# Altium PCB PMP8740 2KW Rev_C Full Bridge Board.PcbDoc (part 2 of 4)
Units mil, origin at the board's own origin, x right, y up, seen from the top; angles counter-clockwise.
Board outline 10366.14 x 5900 mil, 2 copper layers (Top Layer, Bottom Layer), stack 62 mil thick; 355 components, 213 nets, 1059 pads, 574 vias.
Unrouted connection lines stored in the file: 2.
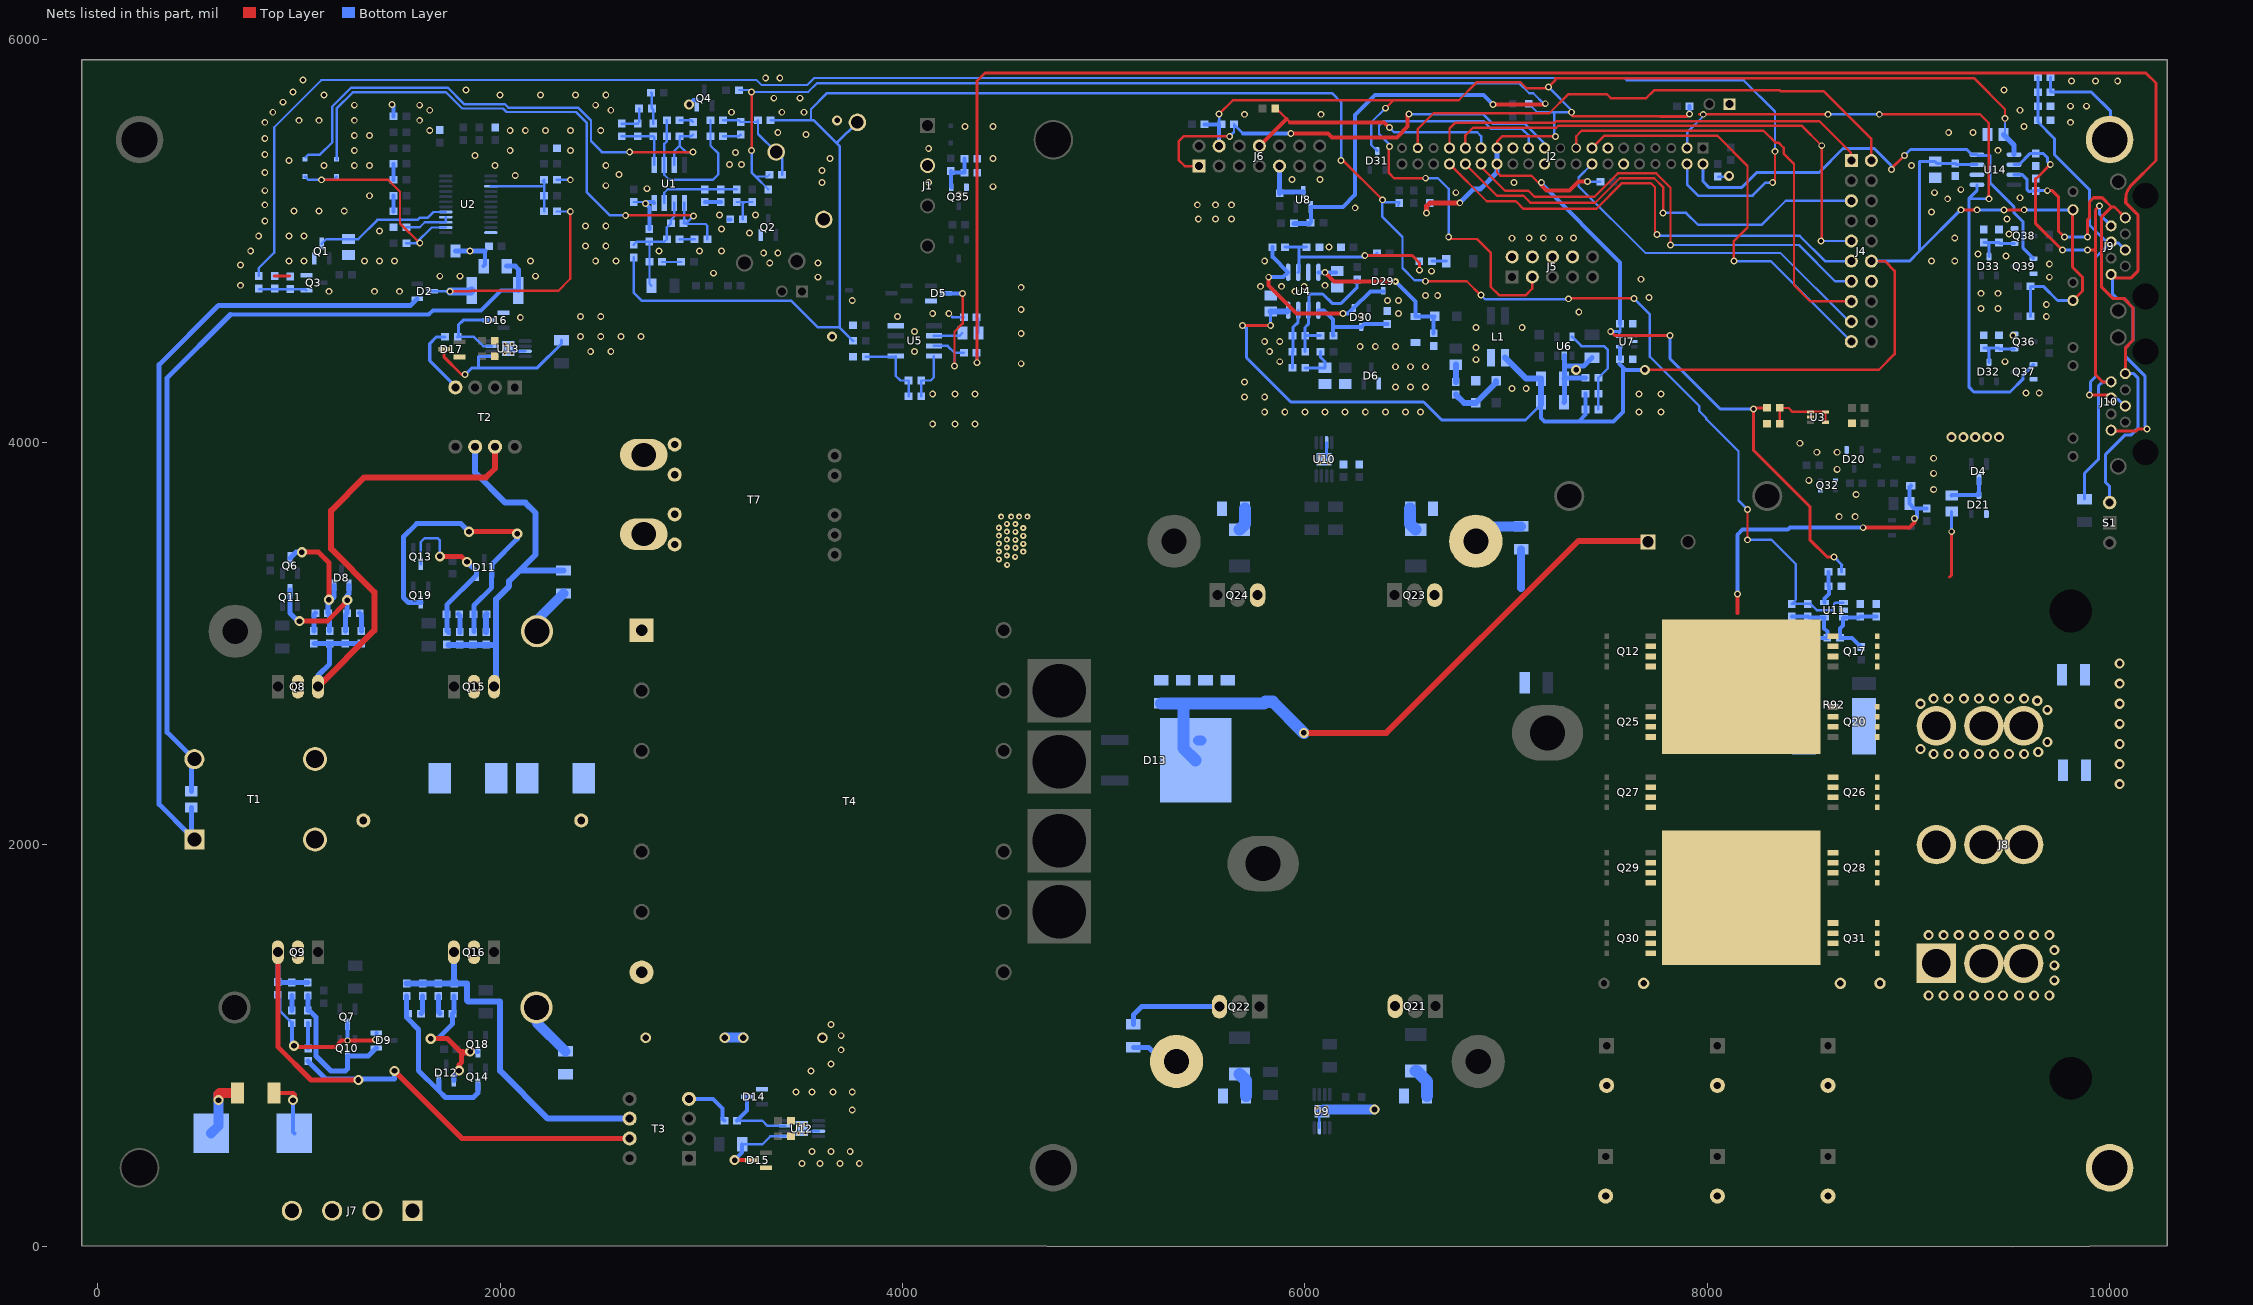
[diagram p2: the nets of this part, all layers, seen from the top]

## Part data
C1: "CAP, CERM, 2200 pF, 50 V, +/- 5%, C0G/NP0, 0603"
C2 C7 C11 C14 C17 C30 C31 C40 C41 C44 C45 C51 C52 C60 C63 C65 C68 C70 C94 C95 C97 C98: "CAP, CERM, 0.1uF, 50V, +/-10%, X7R, 0603"
C3 C10 C22 C23 C24 C42 C43 C61 C62 C69 C71 C73: "CAP, CERM, 1uF, 25V, +/-10%, X7R, 0603"
C4 C88: "CAP, CERM, 2.2uF, 16V, +/-10%, X7R, 0805"
C5 C15 C90 C91 C96: library part C1608X7R2A223K
C6 C16: "CAP, CERM, 0.22uF, 16V, +/-10%, X7R, 0603"
C8: "CAP, CERM, 0.47uF, 16V, +/-10%, X7R, 0805"
C9 C20 C28: "CAP, CERM, 330pF, 50V, +/-5%, C0G/NP0, 0603"
C12: "CAP, CERM, 560pF, 50V, +/-5%, C0G/NP0, 0603"
C13 C36 C37 C38 C39 C46 C47 C49 C50 C66 C67 C72: "CAP, CERM, 0.022uF, 100V, +/-10%, X7R, 0603"
C18: library part CAP_ECQ-E6225KF, "Capacitor, Polyester Film, vvV, ±10%"
C19 C29 C53 C54 C55 C56: library part CAP_ZL_12.5MM_SERIES, "Capacitor, Electrolytic, KZM series, 50V, 105C, 20%"
C21: "CAP, CERM, 22uF, 6.3V, +/-20%, X5R, 0805"
C25: "CAP, CERM, 4.7uF, 25V, +/-10%, X7R, 1206"
C26 C27: "CAP, CERM, 10uF, 10V, +/-20%, X7R, 1206"
C32 C33 C34 C35: "CAP, CERM, 1000pF, 1000V, +/-10%, X7R, 1206"
C48 C58 C59: "CAP, CERM, 10uF, 50V, +/-10%, X7R, 1210"
C57: "CAP, CERM, 0.22 µF, 25 V, +/- 10%, X7R, 0805"
C64 C74 C75 C76: "CAP, CERM, 0.1uF, 250V, +/-10%, X7R, 1206"
C77 C78: "CAP, CERM, 2200pF, 250V, +/-20%, E, Cap, 7x12x9 mm"
C79: "CAP, CERM, 220pF, 50V, +/-5%, C0G/NP0, 0603"
C80: "CAP, CERM, 0.01 µF, 50 V, +/- 10%, X7R, 0603"
C81: "CAP, CERM, 100uF, 10V, +/-20%, X5R, 1206_190"
C82: "CAP, CERM, 1000pF, 50V, +/-10%, X7R, 0603"
C83 C86: "CAP, CERM, 68pF, 50V, +/-5%, C0G/NP0, 0603"
C84 C87 C89 C92 C93: "CAP, CERM, 1uF, 16V, +/-10%, X7R, 0805"
C85: "CAP, CERM, 2700pF, 50V, +/-5%, C0G/NP0, 0603"
C99: "CAP, CERM, 1000 pF, 50 V, +/- 5%, C0G/NP0, 0603"
C100 C101 C102 C103: "CAP, CERM, 470 pF, 500 V, +/- 10%, X7R, 1206"
D1 D3 D28: "Diode, Schottky, 30 V, 0.2 A, SOD-323"
D2 D4 D6 D19 D20 D21 D22 D29 D30 D31 D32 D33: "Diode, Switching, 200V, 0.2A, SOT-23"
D5 D8 D9 D11 D12 D14 D15 D16 D17: "Diode, Schottky, 30V, 0.2A, SOT-23"
D7 D10: "Diode, Ultrafast, 600V, 3A, SMC"
D13: "Diode, Ultrafast, 200V, 8A, DDPAK"
D18: "Diode, Zener, 13 V, 500 mW, SOD-123"
D23 D24 D25 D27: "Diode, Schottky, 60 V, 1 A, SOD-123F"
D26: "Diode, Zener, 5.1 V, 500 mW, SOD-123"
HS1 HS2 HS3 HS4: "Heatsink,  Vertical-mount"
HS5 HS6: "Heatsink, SMT"
J1: "Header (shrouded), 5.08 mm, 4x1, R/A, TH"
J2: "Header, 2mm, 20x2, Gold, TH"
J3 J11: "Header, 100mil, 2x1, Gold, TH"
J4: "Header (shrouded), 100mil, 10x2, Gold plated, TH"
J5: "Header (shrouded), 100mil, 5x2, Gold, TH"
J6: "Header (shrouded), 100 mil, 7x2, Gold plated, TH"
J7: "Header, 4POS, 200mil, Vertical, Tin, TH"
J8: "Header (shrouded), 15 mm, 3x3, R/A, TH"
J9 J10: "RJ-45, Right Angle, Yellow/Green LED, tab up"
J18 J19: "Power Connector, 8AWG, SILVER W/PIN, TH"
L1: library part 744878004, "Coupled inductor, 10 µH, 1 A, 0.14 ohm, +/- 20%, SMD"
L2: "Inductor, Shielded Drum Core, WE-Perm, 2.3uH, 17A, 0.0037 ohm, SMD"
L3: "Inductor, Wirewound, 7.9uH, 60A, SMD"
Q1 Q2 Q3 Q4 Q35 Q36 Q37 Q38 Q39: "MOSFET, N-CH, 50V, 0.22A, SOT-23"
Q5: library part "MMBT2222A, Fairchild Semiconductor", "Transistor, NPN, 40V, 0.15A, SOT-23"
Q6 Q7 Q13 Q14: library part "MMBT3904, Fairchild Semiconductor", "Transistor, NPN, 40V, 0.2A, SOT-23"
Q8 Q9 Q15 Q16: "MOSFET, N-CH, 550V, 17A, TO-220AB"
Q10 Q11 Q18 Q19: library part "MMBT3906, Fairchild Semiconductor", "Transistor, PNP, 40V, 0.2A, SOT-23"
Q12 Q17 Q20 Q25 Q26 Q27 Q28 Q29 Q30 Q31: "MOSFET, N-CH, 60V, 172A, SON 5x6mm"
Q21 Q22 Q23 Q24: library part IPP50R199CP, "MOSFET, N-CH, 150V, 83A, TO-220AB"
Q32: library part "MMDT3904-7-F, Diodes Inc.", "Transistor, Dual NPN, 160 V, 0.2 A, SOT-363"
Q33: library part "MMBT2907A, Fairchild Semiconductor", "Transistor, PNP, 60 V, 0.8 A, SOT-23"
Q34: library part BSS84-7-F, "MOSFET, P-CH, -30 V, -3 A, SOT-23"
R1 R114: "RES, 0 ohm, 1%, 0.1W, 0603"
R2 R31 R33 R51 R55 R56 R57 R63 R66 R80 R111 R115: "RES, 10.0k ohm, 1%, 0.1W, 0603"
R3: "RES, 68.1 k, 1%, 0.1 W, 0603"
R4 R24 R30 R45 R52 R104 R108: "RES, 100k ohm, 1%, 0.1W, 0603"
R5 R6: "RES, 8.25k ohm, 1%, 0.1W, 0603"
R7: "RES, 15.4k ohm, 1%, 0.1W, 0603"
R8: library part CRCW06031R00FKEA
R9 R10 R11: "RES, 49.9k ohm, 1%, 0.1W, 0603"
R12 R39: "RES, 49.9 ohm, 1%, 0.1W, 0603"
R13: "RES, 33.2 k, 1%, 0.25 W, 1206"
R14: "RES, 2.49k ohm, 1%, 0.1W, 0603"
R15 R42: "RES, 60.4k ohm, 1%, 0.1W, 0603"
R16: "RES, 4.64k ohm, 1%, 0.1W, 0603"
R17: "RES, 348 ohm, 1%, 0.1W, 0603"
R18: "RES, 562, 1%, 0.1 W, 0603"
R19: "RES, 2.37k ohm, 1%, 0.1W, 0603"
R20: "RES, 90.9k ohm, 1%, 0.1W, 0603"
R21 R43: library part CRCW060313K0FKEA
R22: "RES, 13.0k ohm, 1%, 0.1W, 0603"
R23 R41 R44 R61: "RES, 47.5 k, 1%, 0.1 W, 0603"
R25 R26 R35 R46 R47 R105 R118 R121: "RES, 4.75k ohm, 1%, 0.1W, 0603"
R27 R28 R49 R58 R59 R60 R83 R84 R93 R94 R123: "RES, 1.00k ohm, 1%, 0.1W, 0603"
R29 R50: "RES, 102 k, 1%, 0.1 W, 0603"
R34: "RES, 16.2, 1%, 1 W, 2512"
R36: library part CRCW12061K00FKEA, "RES, 0 Ohm, 0.25 W, 1206"
R37: "RES, 150 k, 1%, 0.1 W, 0603"
R38 R110: "RES, 33.2 ohm, 1%, 0.1W, 0603"
R40: "RES, 28.0k ohm, 1%, 0.1W, 0603"
R48 R70 R71 R72 R75 R76 R77 R81 R82 R85 R88 R89 R90: "RES, 100 ohm, 1%, 0.1W, 0603"
R53: "RES, 10.0k ohm, 1%, 0.125W, 0805"
R54: "RES, 30.1k ohm, 1%, 0.1W, 0603"
R62: "RES, 105k ohm, 1%, 0.1W, 0603"
R64: "RES, 20.0k ohm, 1%, 0.1W, 0603"
R65 R67 R109 R112 R113: "RES, 22.1k ohm, 1%, 0.1W, 0603"
R68 R125 R126 R127 R128: "RES, 10.0, 1%, 0.75 W, 2010"
R69: "RES, 100k ohm, 5%, 0.125W, 0805"
R73 R74 R86 R87: "RES, 10.0, 1%, 0.25 W, 1206"
R78 R79 R95 R96 R97 R99: "RES, 2.21 ohm, 1%, 0.25W, 1206"
R91: "RES, 47.5 ohm, 1%, 0.125W, 0805"
R92: library part R-WSL3637, "Resistor, precision shunt,  5W, 1%,"
R98: library part RTO020F680R0JTE3, "RES, 1Kohm, 5%, 20W, TH"
R100 R101: "RES, 165k ohm, 1%, 0.1W, 0603"
R102: "RES, 27.4 k, 1%, 0.1 W, 0603"
R103: "RES, 169 k, 1%, 0.1 W, 0603"
R106: "RES, 332 ohm, 1%, 0.1W, 0603"
R107 R119 R122: "RES, 1.00 M, 1%, 0.1 W, 0603"
R116: "RES, 121, 1%, 0.25 W, 1206"
R117 R120: "RES, 100, 1%, 0.1 W, 0603"
R124: library part CRCW06031K00FKEA
RT1 RT2: library part B57153S150M, "Thermistor PTC, 15 ohm, 8.5mm Disc"
S1: "Switch, Slide Flush actuator, SPDT, R/A, TH"
T1: library part CS4200V-01L, "Transformer , Current sense, 1:100, 20 mH, TH"
T2 T3: "Drive Gate Transformer, 900uH"
T4: "Transformer, 3.2mH, TH"
T7: "Transformer, 300uH, TH"
TP1: "Test Point, Compact, Black, TH"
TP2 TP5: "Test Point, Compact, Orange, TH"
TP3 TP6: "Test Point, Compact, Red, TH"
TP4 TP7 TP8 TP13: library part 8600-0-05-80-00-00-03-0, "PCB Pin, solderless Pressfit, Tin over Nickel"
U1: "IC, Precision Dual Operational Amplifiers"
U2: "Green Phase-Shifted Full-Bridge Controller with Synchronous Rectification with Current Control, 97 % Duty Cycle, -40 to +125 degC, 24-pin TSSOP (PW), Green (RoHS & no Sb/Br)"
U3: "Analog Temperature Sensor with Class-AB Output, 5-pin SC-70"
U4: library part TLC2272ACD, "Advanced LinCMOS(TM) Rail-to-Rail Dual Operational Amplifier, 4.4 to 16 V, 0 to 70 degC, 8-pin SOIC (D0008A), Green (RoHS & no Sb/Br)"
U5: library part UCC2900XD, "IC, Advance 8-p Load -Share Controller."
U6: "4.5V to 18V Input, 500mA Synchronous Step Down SWIFT Converter, DBV0005A"
U7: library part TPS71533DCK, "50 mA, 24 V, 3.2-mA Supply Current Low-Dropout Linear Regulator, DCK0005A"
U8: "PRECISION PROGRAMMABLE REFERENCE, DBZ0003A"
U9 U10 U12 U13: "Dual 5-A High-Speed Low-Side Gate Driver, DGN0008D"
U11: library part OPA376AIDBV, "Low-Noise, Low Quiescent Current, Precision Operational Amplifier e-trim Series, DBV0005A"
U14: "CAN Transceiver with Fast Loop Times for Highly Loaded Networks, 85 mA, 5 V, -40 to 125 degC, 8-pin SOIC (D), Green (RoHS & no Sb/Br)"

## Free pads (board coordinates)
  round 196.85 hole 177.17: 0(207.52,393.7) 0(4750,5503.94)
  round 236.22 hole 177.17: 0(207.52,5503.94) 0(4750,393.7)

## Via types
v1: diameter 34, hole 20, Top Layer to Bottom Layer, 367 vias
v2: diameter 50, hole 28, Top Layer to Bottom Layer, 60 vias
v3: diameter 34, hole 20, Top Layer to Bottom Layer, tented both sides, 45 vias
v4: diameter 30, hole 12, Top Layer to Bottom Layer, tented both sides, 34 vias
v5: diameter 50, hole 28, Top Layer to Bottom Layer, tented both sides, 33 vias
v6: diameter 19.68, hole 7.87, Top Layer to Bottom Layer, tented both sides, 20 vias
v7: diameter 34, hole 22, Top Layer to Bottom Layer, 11 vias
v8: diameter 34, hole 15, Top Layer to Bottom Layer, 3 vias
v9: diameter 30, hole 20, Top Layer to Bottom Layer, tented both sides, 1 vias

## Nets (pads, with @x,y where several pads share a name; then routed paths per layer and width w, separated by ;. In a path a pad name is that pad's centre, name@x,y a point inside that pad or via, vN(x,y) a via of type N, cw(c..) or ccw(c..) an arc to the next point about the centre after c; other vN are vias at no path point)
+3V45: C24.1 C92.1 D31.3 J2.27 J2.28 J6.4 R26.2 R31.2 R38.2 R48.2 R51.2 R55.1 R61.1 R115.2 U7.5 U14.5 | length 10673.1
  Top Layer w12: v1(5572.7,5630.63) 5642.07,5700 6440,5700 ; v1(6400,5660) 6440,5700 ; J2.28@6954.76,5383.07 6954.76,5341.73 6971.5,5325 7125,5325 v1@7175,5275 ; J2.27@6954.76,5461.81 6955,5462.05 6955,5495 6980,5520 v1(7245,5520) v1@7250,5520 ; v1(7325,5640) 7325,5625 7330,5620 7765,5620 ; v1@9480,5595 v1(9480,5610) 9480,5655 9325,5810 7245,5810 7245,5800 v1(7210,5765) 7210,5760 7100,5760 7070,5790 6855,5790 6765,5700 6440,5700
  Top Layer w15: v1(7520,4550) 7540,4530 v1(7815,4530) ; 7765,5620 7900,5620 7905,5625 v3(7911.5,5631.5) ; R38.2@8297.28,4170.47 8296.81,4170 8235,4170 v1(8230,4165) 8230,3960 8510,3680 8510,3515 8595,3430 v1(8630,3430)
  Top Layer w20: v1(7175,5290) 7175,5275 7200,5250 7315.51,5250 7360.51,5295 v1(7405,5295)
  Top Layer w25: v1(6605,5140) 6605,5173.5 6621.5,5190 v1(6770,5190)
  Bottom Layer w12: v1(5572.7,5630.63) 5573.66,5629.67 5573.66,5579.92 R61.1@5573.66,5568.9 ; D31.3@6360,5447.24 6330,5477.24 6330,5590 v1(6400,5660) ; R51.2@7112.24,5682.28 7154.53,5640 7239.76,5640 ; v1@7210,5760 v1(7210,5765) 7325,5650 v1(7325,5640) 7239.76,5640 ; v1(7245,5520) 7239.76,5525.24 7239.76,5640 ; v1(7405,5295) R55.1@7468.5,5295 ; U7.5@7562.6,4525.91 7562.6,4545.91 7566.69,4550 C24.1@7566.69,4587.87 ; C92.1@9472.5,5529.38 9480,5536.88 v1(9480,5610)
  Bottom Layer w15: v1(7520,4550) 7566.69,4550 ; v1(7815,4530) 7815,4415 8065,4165 v1(8230,4165) ; v1(8630,3430) 8670,3390 8666.5,3386.5 R48.2@8666.5,3355
  Bottom Layer w20: R26.2@5501.5,5580 5501.57,5579.92 R61.1@5573.66,5579.92 ; J6.4@5573.66,5472.44 R61.1@5573.66,5568.9 ; 6872.09,5259.06 6876.02,5262.99 ; v1(7175,5290) 7180,5290 7180,5280 7566.69,4893.31 C24.1@7566.69,4587.87 ; R115.2@7911.5,5670 v3(7911.5,5631.5) ; v3(7911.5,5631.5) 7905,5625 v3(7911.5,5631.5)
  Bottom Layer w25: v1(6605,5140) 6605,5173.5 R31.2@6620,5188.5 ; v1(6770,5190) 6839.06,5259.06 6872.09,5259.06 ; 6876.02,5262.99 6954.76,5341.73 J2.28@6954.76,5383.07 J2.27@6954.76,5461.81 ; C92.1@9472.5,5529.38 9525.02,5476.86 U14.5@9525.02,5429.38
+5V: C23.1 C26.1 C27.1 C28.1 C84.1 C93.1 C94.1 J4.12 J9.10 J9.12 L1.2 R62.2 R118.1 R121.1 U4.8 U7.4 U14.3 | length 8096.7
  Top Layer w12: v2(7690,4359.45) 8852.4,4359.45 8931.14,4438.19 8931.14,4851.57 8882.72,4900 J4.12@8815.79,4900
  Top Layer w15: v1(5690,4580) 5820,4580 5830,4590 v1(5830,4580) ; v1(9260.32,5155.31) v1(9340,5155.31) ; v1(9475,5155) v1@9575,5155 ; J9.12@9817.72,4704.53 9865,4751.81 9865,4820 9815,4870 9815,5152.6 J9.10@9817.72,5155.31
  Bottom Layer w15: v1(5690,4580) 5700,4570 5710,4570 5710,4420 5930,4200 6590,4200 6680,4110 7096.06,4110 C27.1@7173.27,4187.2 ; v1(5830,4580) C84.1@5830,4650 ; J4.12@8815.79,4900 9005,4900 9055,4950 ; v1(9260.32,5155.31) 9055,4950 ; v1(9340,5155.31) 9340.32,5155 v1(9475,5155) ; U14.3@9339.99,5379.38 9239,5379.38 C94.1@9232.5,5385.88 9141.01,5385.88 C93.1@9132.5,5394.38 9131.89,5395 9055,5395 9055,4950 ; v1@9575,5155 v1(9575.32,5155.31) J9.10@9817.72,5155.31 ; R118.1@9606.5,4625 R121.1@9606.5,4775 9670,4775 9740.47,4704.53 J9.12@9817.72,4704.53
  Bottom Layer w20: C27.1@7173.27,4198.03 7173.27,4121.26 7190.98,4103.54 7361.42,4103.54 ; R62.2@7395.71,4241.34 C28.1@7395.71,4162.6 7395.71,4137.84 7361.42,4103.54 ; 7562.6,4388.11 7580,4370.71 ; U7.4@7562.6,4474.72 7566.69,4470.63 C23.1@7566.69,4412.87 ; v2(7690,4359.45) 7689.45,4360 7590,4360 7590,4360.71 7580,4370.71 ; 7361.42,4103.54 7533.54,4103.54 7580,4150 7580,4370.71
  Bottom Layer w30: C84.1@5830,4650 5911.28,4650 U4.8@5916.79,4655.51 ; L1.2@6995.43,4420.67 7099.96,4316.14 C26.1@7173.27,4316.14 C27.1@7173.27,4198.03 C27.1@7173.27,4187.2
+5VREF: R25.1 R46.1 R60.1 R63.2 R102.2 U8.1 | length 6474.8
  Top Layer w12: v3(3250,5450) 3250,5583.9 3250.04,5583.86 v3(3250.04,5741.34)
  Top Layer w20: v1(6935.08,5678.35) 7190.98,5678.35 v1(7195,5682.36)
  Bottom Layer w10: R46.1@3186.5,5750 3241.38,5750 v3(3250.04,5741.34) 3531.34,5741.34 3575,5785 ; 3269.8,5320 3328.5,5320 R102.2@3338.5,5330
  Bottom Layer w12: v3@3250,5446.1 3250,5339.8 3269.8,5320 R25.1@3332.72,5257.09 ; 3575,5785 7064.65,5785 7115.31,5734.34 7134.99,5734.34 7190.98,5678.35 v1(7195,5682.36)
  Bottom Layer w20: R60.1@6023.66,5087.8 6029.57,5093.7 U8.1@6029.57,5168.5 6188.5,5168.5 6250,5230 6250,5627.13 6347.65,5724.77 6888.65,5724.77 v1(6935.08,5678.35)
  Bottom Layer w25: R63.2@5944.92,5087.8 R60.1@6023.66,5087.8
+390V: J7.1 J7.2 L2.1 R68.1 | length 385.7
  Top Layer w20: R68.1@879.49,765 970,765 980,755 980,735 975,730 v2(970,730)
  Bottom Layer w20: v2(970,730) 975,730 980,735 980,755 970,765 970,571.69 L2.1@976.69,565
-5V: C73.1 C87.1 D24.2 D26.2 U4.4 | length 853.1
  Top Layer w20: v1(6100,4844.49) 6145.47,4799.02 v8(6449.88,4799.02)
  Bottom Layer w20: U4.4@6066.79,4844.49 v1(6100,4844.49) C87.1@6154.49,4844.49 ; v8(6449.88,4799.02) 6550,4698.9 D26.2@6550,4624.47 6550.53,4625 D24.2@6644.88,4625 6640,4620.12 C73.1@6640,4541.5
AVCC: J2.12
"BACKLIGHT P1.0": J2.37 J4.2 | length 2652.3
  Top Layer w12: J2.37@6561.06,5461.81 6561.06,5556.3 6639.8,5635.04 7214.61,5635.04 7309.57,5730 7500,5730 7520,5710 7696.83,5710 7735.67,5748.83 8360.65,5748.83 8364.21,5745.28 8576.81,5745.28 8815.79,5506.3 J4.2@8815.79,5400
CAN_RX: J2.2 Q39.1 U14.4 | length 2321.5
  Top Layer w15: v1(8915,5355) 8915,5360 v1(8980,5425)
  Bottom Layer w15: J2.2@7978.39,5383.07 7978.39,5296.61 8010,5265 8170,5265 8245,5340 8555,5340 8675,5460 8830,5460 8915,5375 v1(8915,5355) ; v1(8980,5425) 9010,5455 9290,5455 9315.62,5429.38 U14.4@9339.99,5429.38 9344.37,5425 9405,5425 9405,5290 9525,5170 9525,5140 9570,5095 9570,4964.65 Q39.1@9622.24,4912.4
CAN_TX: J2.3 Q37.1 U14.1 | length 3561.5
  Top Layer w12: 7960,5630 v1(7980,5630) v1(8600,5630) ; v1(8855,5630) 9355,5630 9400,5585 v1(9400,5210)
  Bottom Layer w12: J2.3@7899.65,5461.81 7899.65,5539.65 7985,5625 v1(7980,5630) ; v1(8600,5630) v1(8855,5630) ; 9300,5210 v1(9400,5210)
  Bottom Layer w15: U14.1@9339.99,5279.38 9340,5250 9300,5210 9300,4275 9325,4250 9505,4250 9570,4315 9570,4335.16 Q37.1@9622.24,4387.4
"CLOCK TEST/SBWTCK": J2.29 J6.8 R106.1 | length 1330.7
  Top Layer w12: R106.1@5852.4,5658.66 5857.52,5658.66 5926.18,5590
  Top Layer w20: J6.8@5773.66,5472.44 5908.7,5607.48 ; 5926.18,5590 6393.5,5590 v3(6420,5563.5)
  Bottom Layer w12: v3(6420,5563.5) 6442.95,5540.55 6856.34,5540.55 6876.02,5520.87 J2.29@6876.02,5461.81
CT+: D2.1 R69.2 T1.1 | length 3964.1
  Bottom Layer w25: T1.1@460.04,2044.96 305,2200 305,4385 597.5,4677.5 ; T1.1@465.04,2039.96 R69.2@465.04,2185 ; 600,4680 1555,4680 D2.1@1587.6,4712.6
CT-: R34.1 R36.1 R69.1 T1.4 | length 4213.9
  Bottom Layer w20: 660,4635 1645,4635 1665,4655 1905,4655 2003.15,4753.15 R34.1@2090.59,4753.15
  Bottom Layer w25: R69.1@465.04,2265 465.04,2410.04 T1.4@479.11,2424.11 ; T1.4@480,2425 T1.4@479.11,2424.11 ; 660,4635 345,4320 345,2558.23 T1.4@479.11,2424.11 ; R36.1@2032.09,4875 2075,4875 2090.59,4859.41 R34.1@2090.59,4753.15
"D4(D0) P1.7": J2.30 J4.13 | length 2352.4
  Top Layer w12: J2.30@6876.02,5383.07 6876.02,5368.98 6995,5250 7111.25,5250 7141.25,5220 7438.85,5220 7554.68,5335.83 7746.1,5335.83 7816.97,5264.96 v3(7816.97,4980)
  Bottom Layer w12: v3(7816.97,4980) 8455,4980 8635,4800 J4.13@8715.79,4800
"D5(D1) P1.6": J2.31 J4.9 | length 2522.6
  Top Layer w10: 7250.24,5563.04 7261.2,5574
  Top Layer w12: J2.31@6797.28,5461.81 6797.28,5524.8 6835.52,5563.04 7250.24,5563.04 ; 7260.2,5572 8467.56,5572 ; 8468.56,5574 v1(8568.94,5473.62) 8568.94,5003.94 v1(8565,5000)
  Bottom Layer w12: v1(8565,5000) J4.9@8715.79,5000
"D6(D2) P1.5": J2.32 J4.5 | length 2270.3
  Top Layer w12: J2.32@6797.28,5383.07 6955.35,5225 7085.96,5225 7120.96,5190 7442.8,5190 7564.62,5311.83 7736.16,5311.83 7781.54,5266.45 v3@7781.54,5140
  Bottom Layer w12: v3(7780,5140) 7815.94,5140 7895,5140 7955,5080 8270,5080 8390,5200 J4.5@8715.79,5200
"D7(D3) P1.4": J2.33 J4.1 | length 2211.1
  Top Layer w12: J2.33@6718.54,5461.81 6718.54,5559.48 6746.1,5587.04 7240.3,5587.04 7248.26,5595 8557.8,5595 8713.36,5439.44 J4.1@8713.36,5400
"DATA_I/O RST/NMI": J2.21 J6.1 R61.2 | length 2271.1
  Top Layer w12: J6.1@5473.66,5372.44 5402.4,5372.44 5372.09,5402.76 5372.09,5495 5371.57,5495 5396.57,5520 v3(5626.14,5520)
  Top Layer w20: v3(5930,5535) 6115,5535 6135,5515 6456.77,5515 6509.88,5568.11 v3@6509.88,5631.1
  Bottom Layer w12: v3(5626.14,5520) 5647.68,5541.54 R61.2@5647.68,5579.92 5692.6,5535 ; v3(6517.76,5631.1) 6885.39,5631.1 6934.89,5581.61 7093.39,5581.61 7190.98,5484.02 J2.21@7190.98,5461.81
  Bottom Layer w20: 5692.6,5535 v3(5930,5535)
"E P1.3": J2.34 J4.11 | length 2435.1
  Top Layer w12: J2.34@6718.54,5383.07 6904.03,5197.58 7049.41,5197.58 7086.99,5160 7447.96,5160 7575.79,5287.83 7719.3,5287.83 7740,5267.13 7740,5041.96 v1(7749.66,5032.3)
  Bottom Layer w12: v1(7749.66,5032.3) 7755.97,5025.99 8459.01,5025.99 8585,4900 J4.11@8715.79,4900
EARTH: C96.2 J8.2 R124.1 TP7.1 TP8.1 | length 556
  Bottom Layer w15: R124.1@9706.5,5815 C96.2@9706.5,5740 9910,5740 10005,5645 10005,5508.94 TP8.1@10000,5503.94
"ENA_FB P4.7": J2.4 R33.2 | length 9356.7
  Top Layer w12: v1(8325,5290) 8336.65,5301.65 v3(8336.65,5446.06)
  Bottom Layer w10: 1110.94,5799.09 1111.85,5800 3275,5800 3300,5775 3525,5775 3560,5810 7588.65,5810 7600.43,5798.21
  Bottom Layer w12: R33.2@800,4826.5 800,4865 877.32,4942.32 877.32,5565.47 1110.94,5799.09 ; 7600.43,5798.21 8181.35,5798.21 8336.65,5642.91 v3(8336.65,5446.06) ; J2.4@7899.65,5383.07 7899.65,5280.35 7954.38,5225.62 8225.62,5225.62 8290,5290 v1(8325,5290)
GATE-A: D17.3 R78.1 U13.5 | length 858.6
  Top Layer w15: D17.3@1722.6,4461.42 1720,4458.82 1720,4425 1808.31,4336.69 v1@1826.69,4336.69
  Bottom Layer w15: v1(1825,4336.69) 1826.69,4336.69 1860,4370 2185,4370 2305,4490 R78.1@2305,4507.09 ; 1891.26,4376.26 1891.26,4426.26 U13.5@1958.5,4426.26
GATE-B: C43.2 D16.3 U13.7 | length 408.9
  Bottom Layer w12: C43.2@1789.19,4523.7 1869.71,4523.7 1915.97,4477.44 U13.7@1958.5,4477.44
  Bottom Layer w15: C43.2@1789.19,4523.7 1792.24,4526.75 1792.24,4582.76 1815.91,4606.42 D16.3@1942.6,4606.42
GATE-C: D15.3 R79.1 U12.5 | length 406.2
  Top Layer w20: v5(3165.28,431.14) D15.3@3245.98,431.14
  Bottom Layer w12: R79.1@3202.68,509.88 3303.07,509.88 3342.44,549.25 3416.26,549.25 U12.5@3417.24,550.24
  Bottom Layer w20: v5(3165.28,431.14) 3202.68,468.54 R79.1@3202.68,509.88
GATE-D: C42.2 D14.3 U12.7 | length 389.7
  Bottom Layer w12: C42.2@3177.09,627.99 3303.07,627.99 3329.65,601.42 U12.7@3417.24,601.42
  Bottom Layer w20: C42.2@3177.09,627.99 3226.3,677.2 D14.3@3226.3,746.1
GND-P: C18.2 C32.2 C33.2 C44.2 C45.2 C46.1 C47.1 C49.1 C50.1 C51.2 C52.2 C77.2 D10.2 J7.3 J7.4 Q15.3 Q16.3 T2.6 T3.6 | length 3709.1
  Bottom Layer w30: C47.1@1535.47,1309.61 C45.2@1614.21,1309.61 C52.2@1692.95,1309.61 C50.1@1771.69,1309.61 ; C46.1@1743.43,2991.73 1822.17,2991.73 1900.91,2991.73 1979.65,2991.73 ; Q16.3@1770,1465 1771.69,1463.31 C50.1@1771.69,1309.61 ; T2.6@1875.79,3977.36 1875.79,3849.21 2025,3700 2125,3700 2175.79,3649.21 2175.79,3440.79 2097.5,3362.5 ; Q15.3@1970,2785 1979.65,2794.65 1979.65,2991.73 ; C32.2@2315,3362.09 2097.91,3362.09 2097.5,3362.5 ; T3.6@2643.62,637.83 2237.17,637.83 2000,875 2000,1220 1840,1220 1835,1225 1835,1310 1772.09,1310 C50.1@1771.69,1309.61 ; 1979.65,2991.73 1979.65,3219.65 2045,3285 2045,3310 2097.5,3362.5
GND-S: C3.1 C4.2 C6.2 C7.2 C8.2 C9.2 C10.2 C11.2 C14.2 C16.2 C17.2 C19.2 C22.2 C23.2 C24.2 C25.2 C26.2 C27.2 C29.2 C34.2 C35.2 C48.2 C53.2 C54.2 C55.2 C56.2 C60.2 C61.2 C62.2 C63.2 C64.2 C65.2 C67.1 C68.2 C69.2 C70.2 C71.2 C73.2 C74.2 C75.2 C76.2 C78.1 C79.2 C80.2 C84.2 C85.2 C87.2 C88.2 C89.2 C90.2 C91.1 C92.2 C93.2 C94.2 C95.2 C97.2 C98.2 C100.2 C101.2 C102.2 C103.2 D5.1 D6.1 D14.1 D15.1 D16.1 D17.1 D20.1 D21.1 D25.2 D26.1 J1.2 J2.13 J2.22 J2.25 J4.14 J5.2 J5.4 J5.6 J5.8 J6.9 J11.1 L1.3 Q1.2 Q2.2 Q3.2 Q4.2 Q21.3 Q22.3 Q23.3 Q24.3 Q32.1 Q32.4 Q35.2 Q36.2 Q37.2 Q38.2 Q39.2 R9.1 R10.1 R11.1 R16.1 R17.1 R18.1 R19.1 R20.1 R22.1 R29.1 R36.2 R47.2 R50.1 R57.1 R58.1 R64.1 R66.1 R92.4 R101.1 R103.1 R107.1 R108.1 R112.1 R114.2 R119.1 R122.1 R123.1 TP1.1 U1.4 U2.24 U3.2 U4.3 U5.4 U6.2 U7.2 U8.3 U9.3 U9.9 U10.3 U10.9 U11.2 U12.3 U12.9 U13.3 U13.9 U14.2 | length 3306.1
  Top Layer w15: 875,4826.5 954.53,4826.5 955,4826.97
  Bottom Layer w12: v6(2041.18,4464.65) 2053.98,4451.85 U13.3@2123.86,4451.85 ; C9.2@2281.54,5304.33 v3(2348.46,5304.33) ; R50.1@2604.37,5583.86 C16.2@2683.11,5583.86 2690.98,5591.73 C17.2@2690.98,5658.66 ; C3.1@2663.43,5194.09 2714.61,5194.09 v3(2722.48,5186.22) ; v6(3499.92,588.62) 3512.72,575.83 U12.3@3582.6,575.83 ; 4246.1,4623.23 4247.67,4621.66 R58.1@4305.51,4621.66 ; U9.3@6072.01,592.32 6072.01,662.2 v6(6084.8,675) ; R47.2@8053.19,5320.08 8104.37,5320.08 v5(8108.31,5324.02)
  Bottom Layer w15: v6(6095,3915) 6107.8,3927.8 U10.3@6107.8,3997.68
  Bottom Layer w20: v3(1462.64,5678.35) 1470.51,5670.47 R18.1@1470.51,5619.29 ; R9.1@1470.51,5146.85 R10.1@1470.51,5225.59 ; R11.1@1470.51,5304.33 R22.1@1470.51,5383.07 ; R36.2@1917.91,4875 1925,4882.09 1925,4950 ; R19.1@2742.17,5060.24 2742.17,5166.54 v3(2722.48,5186.22) 2722.48,5194.09 2761.14,5194.09 U1.4@2765.59,5189.65 ; v5(2939.02,5678.35) 2960.67,5700 Q4.2@2980.35,5700 ; C6.2@3017.76,5194.09 R29.1@3096.5,5194.09 ; C7.2@3135.87,5107.48 C7.2@3143.74,5107.48
  Bottom Layer w25: C4.2@1778.23,4950 1925,4950 ; C34.2@5148.46,1106.29 5148.46,1155 5148.9,1155 5188.9,1195 Q22.3@5575,1195 ; J6.9@5873.66,5372.44 5874.06,5372.05 R66.1@5874.06,5237.4 5879.96,5243.31 U8.3@5992.17,5243.31 ; C27.2@7287.44,4198.03 7289.41,4200 C26.2@7289.41,4318.11 ; C26.2@7287.44,4316.14 C26.2@7289.41,4318.11 ; U6.2@7289.41,4430.31 7289.41,4379.13 ; R64.1@7395.71,4320.08 7291.38,4320.08 C26.2@7289.41,4318.11 ; C25.2@7427.2,4420.47 7385.87,4379.13 7289.41,4379.13 ; C26.2@7289.41,4318.11 7289.41,4379.13
  Bottom Layer w39.37: 7075,3275 C35.2@7075,3467.91
  Bottom Layer w50: v6(6084.8,675) 6092.68,682.87 C60.2@6202.91,682.87 C61.2@6281.65,682.87 v5(6345.91,682.87)
  other v1: 3500,415 3590,415 3690,415 3785,415 3550,475 3645,475 3740,475 3750,680 3470,770 3550,770 3655,770 3750,770 3545,875 3645,910 3695,980 3695,1050 3645,1105 4150,4090 4260,4090 4360,4090 5800,4150 5900,4150 6000,4150 6100,4150 6200,4150 6300,4150 6400,4150 6500,4150 6575,4150 7660,4150 7770,4150 5700,4225 5800,4225 4150,4240 4260,4240 4360,4240 7660,4240 7770,4240 9585,4245 9650,4245 7030,4267.68 7100,4267.68 6450,4275 6525,4275 6600,4275 5700,4300 6450,4375 6525,4375 6600,4375 4590,4390 5875,4400 9480,4400 6850,4410 2450,4450 2550,4450 4060,4450 5825,4450 6850,4470 6275,4475 6350,4475 6450,4475 5800,4500 5875,4500 2400,4525 2500,4525 2600,4525 2700,4525 9520,4530 4590,4540 4060,4550 6850,4570 7080,4570 2100,4620 2400,4625 2500,4625 3975,4625 9685,4625 6280,4630 4150,4640 4230,4640 6465,4640 7361.37,4646.99 4590,4660 9360,4665 9445,4665 9685,4685 3750,4705 6410,4705 6465,4705 7710,4720 6600,4730 6660,4730 9360,4740 9445,4740 1150,4750 1375,4750 1500,4750 5950,4750 4590,4770 5780,4775 5883.52,4775 710,4780 6100.06,4780 7670,4810 3580,4820 9700,4820 1700,4825 1800,4825 2175,4825 3060,4840 6630,4850 710,4880 9700,4885 3340,4890 3580,4890 950,4900 1025,4900 1325,4900 1400,4900 1475,4900 2150,4900 2475,4900 2575,4900 5800,4900 9115,4900 9230,4900 9485,4925 9345,4935 3310,4940 3380,4940 760,4950 2790,4950 2990,4950 3100,4950 2425,4975 2525,4975 7030,5013.76 7265.35,5013.76 7115,5015 7185,5015 7335,5015 9230,5015 800,5025 950,5025 1025,5025 9500,5035 3240,5040 1400,5050 3100,5060 2425,5075 2525,5075 830,5100 5470,5110 5555,5110 5635,5110 9490,5110 3090,5130 3270,5130 9115,5145 975,5150 1100,5150 1225,5150 6250,5165 830,5180 5465,5180 5555,5180 5635,5180 9195,5210 9555,5215 1350,5225 4280,5230 6750,5240 9130,5240 830,5250 9260,5255 2730,5260 4450,5270 2525,5275 3600,5290 4130,5290 7040,5290 5935,5305 6075,5305 2075,5325 2590,5330 830,5340 3600,5350 1125,5375 1275,5375 1350,5375 1975,5375 2525,5375 9015,5375 3140,5380 3200,5380 950,5400 3640,5410 4450,5410 1875,5425 830,5430 3170,5440 1275,5450 2050,5450 2350,5450 9445.42,5450.84 4130,5460 830,5510 1275,5525 1350,5525 3520,5530 3380,5540 9200,5540 9320,5540 1650,5550 2050,5550 2125,5550 2225,5550 2350,5550 2500,5550 4310,5570 4450,5570 9575,5570 830,5590 9805,5590 1000,5600 1100,5600 1275,5600 1600,5600 5700,5630 6080,5630 870,5640 3150,5640 3400,5640 3510,5640 1650,5650 2550,5650 9555,5650 9805,5670 9885,5670 1275,5675 1600,5675 2475,5675 920,5690 3360,5710 3490,5710 1125,5725 2000,5725 2200,5725 2375,5725 2525,5725 970,5740 1830,5750 9475,5750 9810,5795 9930,5795 10040,5795 1020,5800 3320,5810 3390,5810
  other v3: 5996.4,4773.98 1850,4950 6120,4970
  other v4: 4520,3390 4479.17,3417.36 4560,3430 4518.54,3437.05 4600,3455.63 4479.17,3456.73 4560.63,3475.31 4518.54,3476.42 4600,3495 4479.17,3496.1 4560.63,3514.69 4518.54,3515.79 4600,3534.37 4479.17,3535.47 4560.63,3554.06 4518.54,3555.16 4600,3573.74 4479.17,3574.84 4560.63,3593.43 4518.54,3594.53 4490,3630 4540,3630 4580,3630 4620,3630
  other v5: 9213.78,4025 9272.83,4025 9331.89,4025 9390.94,4025 9450,4025 7348.46,4359.45 3650,4525 3675,5600
  other v6: 3482.2,565 3517.64,565 3482.2,612.24 3517.64,612.24 6061.18,657.28 6108.43,657.28 6061.18,692.72 6108.43,692.72 6071.38,3897.28 6118.62,3897.28 6071.38,3932.72 6118.62,3932.72 2023.46,4441.02 2058.9,4441.02 2023.46,4488.27 2058.9,4488.27
  other v7: 8655,3630 8735,3630 8740,3740 9125,3765 8505,3810 9125,3845 8645,3865 9125,3920 8545,3950 8645,3950 8460,3995
"INRUSH_RELAY P2.6": J2.23 J5.3 | length 2344
  Top Layer w12: v3@6417.1,5470 6417.1,5338.06 6442.95,5312.2 v3(6600.43,5312.2) ; v3(6714.61,5020) 6724.61,5010 6855.39,5010 6923.27,4942.13 6923.27,4772.83 6966.34,4729.76 7096.73,4729.76 7130.35,4763.39 J5.3@7130.35,4821.26
  Bottom Layer w12: v3(6420,5470) 6420,5480 6368.15,5531.85 6368.15,5573.55 6390.27,5595.67 6886.88,5595.67 6924.94,5557.61 7079.44,5557.61 7112.24,5524.8 7112.24,5493.31 ; v3(6600.43,5312.2) 6660,5312.2 6660,5313.38 6714.61,5258.78 v3@6714.61,5024.8
IOUT: C66.1 R4.1 R35.2 R39.1 R56.2 R100.1 TP6.1 U11.1 | length 10080.4
  Top Layer w12: v1@6180,5410 v1(6385,5205) ; v1(6600,4800) 6804.76,4800 6875,4729.76 v1(6875,4731.61) ; v1(7310,4712.85) 7310,4715 v1(7635,4715) ; v1(8199.68,3515) 8199.68,3564.69 8200,3565 v1(8200,3665)
  Bottom Layer w12: R4.1@2663.43,4918.5 2663.43,4743.31 2702.8,4703.94 3446.06,4703.94 3579.17,4570.83 3687.05,4570.83 ; R39.1@3344.53,5599.61 3545,5599.61 ; R56.2@3754.33,4503.55 3687.05,4570.83 ; TP6.1@3775.63,5589.76 3677.2,5491.34 3667.36,5491.34 ; v1(6180,5400) 6180,5690 6135,5735 3625,5735 3545,5655 3545,5599.61 ; R35.2@6462.64,5174.41 6470,5191.95 6398.05,5191.95 v1(6385,5205) 6385,5120 6485,5020 6485,4865 6545,4805 6595,4805 v1(6600,4800) ; v1(6875,4731.61) 6896.61,4710 7312.85,4710 v1(7310,4712.85) ; v1(7635,4715) 7715,4635 7715,4425 7960,4180 7960,4155 7995,4120 7995,4115 8155,3955 8155,3710 v1(8200,3665) ; v1(8199.68,3515) 8319,3515 8440,3394 8440,3216.5 R100.1@8420,3196.5 C66.1@8500,3196.5 8513.5,3196.5 8545,3165 8625,3165 8630,3170 8630,3195 8637.4,3202.4 U11.1@8677.24,3202.4 ; 3545,5599.61 3559.09,5599.61 3667.36,5491.34 ; 3667.36,5491.34 3687.05,5471.65 3687.05,4570.83
"LED_GREEN P3.0": J2.17 J4.15 | length 2159.3
  Top Layer w12: J2.17@7348.46,5461.81 7348.46,5520.87 7375.65,5548.05 8265.79,5548.05 8266.17,5548.43 8279.35,5548.43 8338.72,5489.06 8354.46,5489.06 8379.65,5463.87 8379.65,5434.56 8431.14,5383.07 8431.14,4780.71 8511.85,4700 J4.15@8715.79,4700
"LED_RED P3.2": J2.15 J4.19 | length 2111.8
  Top Layer w12: J2.15@7427.2,5461.81 7489.44,5524.05 8049.63,5524.05 8200,5373.68 8200,5067.07 8132.24,4999.31 v3(8132.24,4900)
  Bottom Layer w12: v3(8132.24,4900) 8315.79,4900 J4.19@8715.79,4500
"LED_YELLOW P3.1": J2.16 J4.17 | length 1772.4
  Bottom Layer w10: J2.16@7427.2,5383.07 7360,5315.87 7360,5273.11 7693.11,4940 8365,4940 8705,4600 J4.17@8715.79,4600
LOAD_SHARE_BUS: J9.8 J10.8 R59.1 | length 9570.6
  Top Layer w15: v1(4370,4395) 4370,5795 4410,5835 10180,5835 10230,5785 10230,5400 10109.29,5279.29 ccw(c10180,5208.58) 10080,5208.58 10080,5190 10140,5130 10140,4850 10105,4815 J9.8@10026.93,4815 ; J10.8@10007.48,4059.45 10011.93,4055 10130,4055 10140,4065 v1(10185,4065)
  Bottom Layer w15: R59.1@4368.5,4444.49 4370,4443 v1(4370,4395) ; J9.8@10007.48,4834.45 10015,4826.93 10015,4735 10035,4715 10070,4715 10115,4670 10115,4505 10077.56,4467.56 10077.56,4427.44 10175,4330 10175,4075 v1(10185,4065)
NetC1_1: C1.1 C2.1 D1.1 U1.1 | length 2866.2
  Top Layer w12: v3(2624.06,5127.17) 2958.07,5127.17 v3(2960.59,5124.65)
  Bottom Layer w12: D1.1@1187.05,5406.69 1187.05,5658.66 1268.1,5739.72 1730.79,5739.72 1811.85,5658.66 2013.82,5658.66 2031.19,5641.29 2377.26,5641.29 2429.52,5589.03 2429.52,5242.96 2545.32,5127.17 v3(2624.06,5127.17) ; C1.1@2911.46,5087.8 C1.1@2919.72,5087.8 ; U1.1@2915.59,5189.65 2915.59,5091.93 C1.1@2919.72,5087.8 ; v3(2960.59,5124.65) 2923.74,5087.8 C1.1@2919.72,5087.8 ; C2.1@3029.57,5009.06 3029.57,5075.98 3020.91,5084.65 2922.87,5084.65 C1.1@2919.72,5087.8
NetC1_2: C1.2 R3.1 R4.2 R13.1 R19.2 R21.1 U1.2 | length 596.2
  Bottom Layer w12: R4.2@2663.43,4981.5 2679.17,4997.24 R19.2@2742.17,4997.24 ; R13.1@2752.01,4777.76 2742.17,4787.6 R21.1@2742.17,4895.87 R19.2@2742.17,4997.24 ; U1.2@2865.59,5189.65 2865.59,5121.65 2848.46,5104.53 C1.2@2848.46,5087.8 2828.78,5068.11 R3.1@2828.78,5009.06 2816.97,4997.24 R19.2@2742.17,4997.24
NetC2_2: C2.2 R3.2 | length 74.8
  Bottom Layer w12: R3.2@2891.77,5009.06 C2.2@2966.57,5009.06
NetC5_2: C5.2 R21.2 | length 94.5
  Bottom Layer w12: R21.2@2805.16,4895.87 C5.2@2899.65,4895.87
NetC6_1: C6.1 R23.1 R29.2 U1.3 | length 417.1
  Bottom Layer w12: U1.3@2815.59,5189.65 2815.59,5239.96 2832.72,5257.09 C6.1@3017.76,5257.09 R29.2@3096.5,5257.09 R23.1@3175.24,5257.09
NetC7_1: C7.1 R23.2 R24.1 | length 168.6
  Bottom Layer w12: R23.2@3175.24,5194.09 3214.61,5194.09 ; C7.1@3206.73,5107.48 3206.73,5186.22 3214.61,5194.09 ; R24.1@3253.98,5194.09 3214.61,5194.09
NetC8_1: C8.1 Q1.3 U2.5 | length 681
  Bottom Layer w12: Q1.3@1113.54,4987.4 1135.19,5009.06 1245.47,5009.06 C8.1@1246.1,5009.68 1294.68,5009.68 1390,5105 1590,5105 1599.92,5114.92 1638.98,5114.92 1668.17,5144.1 U2.5@1729.68,5144.1
NetC9_1: C9.1 R8.1 R27.1 U2.15 | length 425
  Bottom Layer w12: U2.15@1954.09,5272.05 2211.03,5272.05 ; C9.1@2211.03,5296.82 C9.1@2218.54,5304.33 R8.1@2218.54,5225.59 R27.1@2218.54,5146.85
NetC11_1: C11.1 Q3.1 R33.1 R108.2 | length 236.5
  Bottom Layer w12: R33.1@802.93,4760.57 875,4760.57 875.45,4761.02 C11.1@956.06,4761.02 1030.86,4761.02 Q3.1@1036.77,4755.12
NetC12_1: C12.1 C13.1 D3.1 U1.7 | length 2668.2
  Top Layer w12: v3(2643.74,5442.13) v3(2958.7,5442.13)
  Bottom Layer w12: D3.1@1033,5416 1044.85,5427.85 1102.89,5427.85 1165.05,5490.01 1165.05,5667.77 1258.99,5761.72 1739.91,5761.72 1820.96,5680.66 2022.93,5680.66 2040.3,5663.29 2386.37,5663.29 2451.52,5598.15 2451.52,5496.55 2505.94,5442.13 v3(2643.74,5442.13) ; U1.7@2865.59,5378.65 2865.59,5447.44 2891.77,5473.62 ; v3(2958.7,5442.13) 2923.27,5442.13 2891.77,5473.62 ; C13.1@2958.7,5528.74 2950.83,5520.87 C12.1@2891.77,5520.87 2891.77,5473.62
NetC12_2: C12.2 R37.1 R40.2 R43.1 U1.6 | length 850.6
  Bottom Layer w12: R37.1@2828.78,5599.61 C12.2@2828.78,5520.87 2828.78,5496.17 2815.59,5482.98 U1.6@2815.59,5378.65 2815.59,5329.33 2840.59,5304.33 3057.13,5304.33 3084.68,5331.89 3084.68,5363.39 3084.68,5434.25 3045.31,5473.62 R43.1@3045.31,5520.87 R40.2@3045.32,5599.61
NetC13_2: C13.2 R37.2 | length 70.2
  Bottom Layer w12: R37.2@2891.77,5599.61 2950.83,5599.61 C13.2@2958.7,5591.73
NetC14_1: C14.1 R38.1 U3.1 U3.4 U3.5 | length 364.3
  Top Layer w12: C14.1@8360.28,4091.73 8360.28,4169.53 8360.75,4170 8405,4170 8424.41,4150.59 U3.1@8512.6,4150.59 U3.5@8587.4,4150.59 U3.4@8587.4,4099.41
NetC15_1: C15.1 R39.2 R40.1 R102.1 TP5.1 | length 499
  Bottom Layer w12: R40.1@3108.31,5599.61 3187.05,5599.61 C15.1@3194.92,5591.73 3273.66,5591.73 R39.2@3281.54,5599.61 3281.54,5532.68 TP5.1@3372.09,5442.13 3401.5,5412.72 R102.1@3401.5,5330
NetC15_2: C15.2 R43.2 | length 89.9
  Bottom Layer w12: R43.2@3108.31,5520.87 3187.05,5520.87 C15.2@3194.92,5528.74
NetC16_1: C16.1 R44.1 R50.2 U1.5 | length 301.3
  Bottom Layer w12: R50.2@2604.37,5520.87 C16.1@2683.11,5520.87 R44.1@2761.85,5520.87 2765.59,5517.13 U1.5@2765.59,5378.65
NetC17_1: C17.1 R44.2 R45.1 | length 158.4
  Bottom Layer w12: R45.1@2750.04,5737.4 2753.98,5733.46 C17.1@2753.98,5658.66 2761.85,5650.79 R44.2@2761.85,5583.86
NetC18_1: C18.1 L2.2 R68.2 T1.2 | length 362.8
  Top Layer w50: v2(600,730) 600,760 605,765 R68.2@690.51,765
  Bottom Layer w50: L2.2@563.31,565 600,601.69 600,760 v2(600,730)
NetC20_1: C20.1 R54.2 U5.8 | length 254.2
  Bottom Layer w12: C20.1@4092.91,4227.96 R54.2@4092.91,4306.7 4140.16,4306.7 4155.42,4321.96 U5.8@4155.42,4428.55
NetC20_2: C20.2 R54.1 R57.2 U5.1 | length 401.2
  Bottom Layer w12: R57.2@3817.32,4424.81 3962.68,4424.81 U5.1@3966.42,4428.55 3966.42,4329.81 3989.53,4306.7 R54.1@4029.92,4306.7 C20.2@4029.92,4227.96
NetC21_1: C21.1 U5.6 | length 147.5
  Bottom Layer w12: U5.6@4155.42,4528.55 4282.64,4528.55 C21.1@4297.01,4542.92
NetC21_2: C21.2 R58.2 | length 82.3
  Bottom Layer w12: R58.2@4368.5,4621.66 4377.01,4613.15 C21.2@4377.01,4542.92
NetC28_2: C28.2 R62.1 R64.2 U6.5 | length 521.7
  Bottom Layer w12: U6.5@7326.81,4524.8 7374.06,4477.56 7486.26,4477.56 7505.94,4457.87 7505.94,4367.32 R64.2@7458.7,4320.08 C28.2@7458.7,4162.6
NetC30_1: C30.1 R71.1 | length 90.9
  Bottom Layer w25: C30.1@1073.58,3062.36 1073.58,3142.09 R71.1@1081.46,3149.96
NetC30_2: C30.2 C36.1 C38.1 C40.2 J18.1 Q8.3 Q15.2 T2.7 T7.2 T7.3 | length 2584.4
  Top Layer w30: Q8.3@1095,2785 1375,3065 1375,3255 1160,3470 1160,3660 1325,3825 1929.72,3825 1974.21,3869.49 T2.7@1974.21,3977.36
  Bottom Layer w25: C30.2@1073.58,2999.37 C36.1@1152.32,2999.37 ; Q8.3@1095,2760 Q8.3@1110,2745 ; Q8.3@1095,2785 1095,2840 1152.32,2897.32 C36.1@1152.32,2999.37 ; C40.2@1309.8,2999.37 C38.1@1231.06,2999.37 C36.1@1152.32,2999.37
NetC31_1: C31.1 R70.1 | length 74.8
  Bottom Layer w25: R70.1@965.04,1175.87 C31.1@965.04,1250.67
NetC31_2: C31.2 C37.1 C39.1 C41.2 Q9.3 Q16.2 T3.7 T4.6 | length 3061.2
  Top Layer w25: Q9.3@895,1465 895,995 1060,830 v2@1290,830 ; v2(1475,875) 1810.59,539.41 T3.7@2643.62,539.41
  Bottom Layer w25: Q9.3@881.46,1451.46 Q9.3@895,1465 C37.1@895,1316.5 ; C37.1@897.83,1313.66 C31.2@965.04,1313.66 C39.1@1043.78,1313.66 ; C41.2@1045,923.5 1133.5,835 1475,835 v2(1475,875)
  other v2: 1295,830
NetC32_1: C32.1 HS1.1 | length 242.3
  Bottom Layer w50: HS1.1@2183.23,3060.21 2183.23,3116.14 C32.1@2315,3247.91
NetC33_1: C33.1 HS2.2 | length 278
  Bottom Layer w50: HS2.2@2180,1190 2180,1117.09 C33.1@2325,972.09
NetC34_1: C34.1 HS3.1 | length 224.8
  Bottom Layer w25: C34.1@5147.22,992.12 5222.88,992.12 5244.53,970.47 HS3.1@5363.03,970.47
NetC35_1: C35.1 HS4.1 | length 256.1
  Bottom Layer w50: HS4.1@6849.76,3507.68 6924.17,3582.09 C35.1@7075,3582.09
NetC36_2: C36.2 D8.2 Q6.3 R71.2 | length 653.3
  Top Layer w25: v5(1014.53,3453.11) 1097.2,3453.11 1148.39,3401.93 v5(1148.39,3216.89)
  Bottom Layer w25: Q6.3@955.47,3423.58 985,3453.11 v5(1014.53,3453.11) ; C36.2@1152.32,3062.36 1152.32,3142.09 R71.2@1144.45,3149.96 1144.45,3201.14 1173.98,3230.67 D8.2@1173.98,3288.74
NetC37_2: C37.2 D9.2 Q7.3 R70.2 | length 827.9
  Top Layer w20: v5@980.79,995 1181.81,995 1211.81,1025 1241.06,1025 1374.8,1025 1376.06,1026.26 v3(1379.8,1030)
  Bottom Layer w12: C37.2@886.3,1250.67 905.98,1230.98 905.98,1171.93 R70.2@965.04,1112.87
  Bottom Layer w20: R70.2@965.04,1112.87 965.04,1009.96 v5(975,1000) ; Q7.3@1240.63,1106.97 1240.63,1026.69 v9(1241.06,1026.26) ; v3(1379.8,1030) 1376.06,1026.26 1384.33,1034.53 D9.2@1384.33,1063.66
NetC38_2: C38.2 D8.1 Q11.3 R76.2 | length 690.4
  Top Layer w25: v5(1002.72,3110.59) 1140.51,3110.59 v5@1238.94,3209.02
  Bottom Layer w25: Q11.3@955.47,3266.1 955.47,3149.96 994.84,3110.59 v5(1002.72,3110.59) ; C38.2@1231.06,3062.36 1231.06,3142.09 R76.2@1238.94,3149.96 1238.94,3209.02 1238.94,3236.58 1248.78,3246.42 D8.1@1248.78,3288.74
  other v5: 1240,3215
NetC39_2: C39.2 D9.1 Q10.3 R77.2 | length 737.2
  Bottom Layer w25: C39.2@1043.78,1250.67 R77.2@1043.78,1175.87 1050.99,1175.87 1084.98,1141.88 1084.98,949.49 1159.47,875 1230,875 1240.63,885.63 Q10.3@1240.63,949.49 1344.96,949.49 D9.1@1384.33,988.86
NetC40_1: C40.1 R76.1 | length 90.9
  Bottom Layer w25: R76.1@1301.93,3149.96 1309.8,3142.09 C40.1@1309.8,3062.36
NetC41_1: C41.1 R77.1 | length 126.9
  Bottom Layer w20: R77.1@1043.78,1112.87 1045,1111.65 C41.1@1045,986.5
NetC42_1: C42.1 T3.4 | length 250
  Bottom Layer w20: T3.4@2938.9,736.26 3057.01,736.26 3106.22,687.05 3106.22,635.87 C42.1@3114.09,627.99
NetC43_1: C43.1 T2.4 | length 355.3
  Bottom Layer w15: C43.1@1726.2,4523.7 1683.7,4523.7 1650,4490 1650,4405 T2.4@1777.36,4277.64
NetC44_1: C44.1 R82.1 | length 94.8
  Bottom Layer w25: R82.1@1793.05,3145 1800,3138.05 1800,3076.89 C44.1@1800,3053.05
NetC45_1: C45.1 R81.1 | length 89.9
  Bottom Layer w25: R81.1@1606.34,1160 1614.21,1167.87 C45.1@1614.21,1246.61
NetC46_2: C46.2 D11.2 Q13.3 R82.2 | length 877
  Top Layer w25: v5(1700.12,3432.68) 1807.32,3432.68 v5(1835,3405)
  Bottom Layer w12: Q13.3@1605.63,3394.29 1605.63,3503.54 1625.31,3523.23 1688.31,3523.23 1700.12,3511.42 v5(1700.12,3432.68)
  Bottom Layer w25: C46.2@1743.43,3054.72 1735,3063.15 1735,3191.97 D11.2@1883.19,3340.16 1883.19,3356.81 v5(1835,3405)
NetC47_2: C47.2 D12.2 Q14.3 R81.2 | length 847.6
  Bottom Layer w25: C47.2@1535.47,1246.61 1535.47,1140.31 1594.53,1081.26 1594.53,876.54 1694.92,776.14 ; D12.2@1694.92,827.32 1694.92,776.14 ; Q14.3@1889.8,807.64 1889.8,766.3 1866.18,742.68 1728.39,742.68 1694.92,776.14
NetC49_2: C49.2 D11.1 Q19.3 R89.2 | length 1593.5
  Top Layer w25: v2(1845,3555) 2075,3555 v5(2085,3545)
  Bottom Layer w25: Q19.3@1605.63,3202.36 1544.61,3202.36 1520,3226.97 1520,3530 1585,3595 1805,3595 v2(1845,3555) ; C49.2@1870,3059.45 1870,3189.17 1957.99,3277.17 D11.1@1957.99,3340.16 ; D11.1@1960,3331.89 1960,3395 2085,3520 v5(2085,3545)
NetC50_2: C50.2 D12.1 Q18.3 R90.2 | length 717.7
  Top Layer w25: v5(1655,1035) 1738.03,1035 1802.01,971.02 1815,971.02 1807.13,963.15 ; v5(1795.32,876.54) 1795.32,904.09 1807.13,915.91 1807.13,963.15 ; v5(1850.43,971.02) 1842.56,963.15 1807.13,963.15
  Bottom Layer w20: v5(1850.43,971.02) 1881.93,971.02 1880.94,970.04 Q18.3@1889.8,970.04
  Bottom Layer w25: v5(1655,1035) 1690,1035 1763.82,1108.82 R90.2@1763.82,1160 1771.69,1167.87 C50.2@1771.69,1246.61 ; D12.1@1769.72,827.32 1769.72,850.94 v5(1795.32,876.54)
NetC51_1: C51.1 R89.1 | length 89.1
  Bottom Layer w30: C51.1@1930,3056.5 1930,3143.5 R89.1@1931.5,3145
NetC52_1: C52.1 R90.1 | length 89.9
  Bottom Layer w25: C52.1@1692.95,1246.61 1692.95,1167.87 R90.1@1700.83,1160
NetC57_1: C57.1 D18.2 HS5.1 HS6.1 Q12.1 Q12.2 Q12.3 Q17.1 Q17.2 Q17.3 Q20.1 Q20.2 Q20.3 Q25.1 Q25.2 Q25.3 Q26.1 Q26.2 Q26.3 Q27.1 Q27.2 Q27.3 Q28.1 Q28.2 Q28.3 Q29.1 Q29.2 Q29.3 Q30.1 Q30.2 Q30.3 Q31.1 Q31.2 Q31.3 R52.2 RT1.2 RT2.1 | length 1724.1
  Top Layer w20: 8150,3150 v1(8150,3245) ; HS5.1@8169.25,2785 HS5.1@8285,2900.75 ; v1(8775,3575) 9005,3575 9030,3600 v1(9030,3620)
  Bottom Layer w20: v1(8150,3245) 8150,3540 8175,3565 8400,3565 8410,3575 v1(8775,3575) ; D18.2@9011.99,3783.51 9005,3776.52 C57.1@9005,3695 9028.5,3671.5 9042,3671.5 ; v1(9030,3620) 9035,3620 9042,3627 9042,3671.5 ; R52.2@9090,3671.5 9042,3671.5
NetC58_1: C58.1 C59.1 J8.1 Q17.5 Q17.6 Q17.7 Q17.8 Q20.5 Q20.6 Q20.7 Q20.8 Q26.5 Q26.6 Q26.7 Q26.8 Q28.5 Q28.6 Q28.7 Q28.8 Q31.5 Q31.6 Q31.7 Q31.8 R53.2 RT2.2 | length 329.1
  Top Layer w15: 9205,3330 9215,3340 v1(9215,3555)
  Bottom Layer w15: v1(9215,3555) R53.2@9215,3655
  other v2: 9100,1250 9175,1250 9250,1250 9325,1250 9400,1250 9470,1250 9550,1250 9625,1250 9700,1250 9725,1325 9725,1400 9725,1475 9100,1550 9175,1550 9250,1550 9325,1550 9400,1550 9475,1550 9550,1550 9625,1550 9700,1550 10050,2300 10050,2400 10050,2500 10050,2600 10050,2700 10050,2800 10050,2900
NetC58_2: C58.2 C59.2 J8.3 R92.2
  other v2: 9125,2450 9200,2450 9275,2450 9350,2450 9425,2450 9500,2450 9575,2450 9645,2460 9060,2475 9690,2510 9690,2670 9060,2700 9640,2715 9125,2725 9200,2725 9275,2725 9350,2725 9425,2725 9500,2725 9575,2725
NetC64_1: C64.1 C74.1 C75.1 C76.1 D13.4 R98.1 | length 3227.6
  Top Layer w30: v2(5995,2555) 6405,2555 7360,3510 7700,3510 R98.1@7705,3505
  Bottom Layer w20: C74.1@5268.09,2701.91 C74.1@5286,2701.91
  Bottom Layer w50: D13.4@5467.52,2517.87 D13.4@5485,2517.87
  Bottom Layer w60: C74.1@5286,2701.91 C76.1@5396,2701.91 ; D13.4@5456.51,2419 5396,2479.51 C76.1@5396,2701.91 ; v2(5995,2555) 5840,2710 5805,2710 5796.91,2701.91 C64.1@5616,2701.91 C75.1@5506,2701.91 C76.1@5396,2701.91
NetC65_1: C65.1 R48.1 U11.5 | length 162.4
  Bottom Layer w20: U11.5@8582.76,3202.4 8582.76,3222.76 8605,3245 8605,3283.5 C65.1@8603.5,3285 R48.1@8603.5,3355
NetC66_2: C66.2 C99.2 R94.1 R100.2 U11.4 | length 398
  Bottom Layer w20: R100.2@8420,3133.5 C66.2@8500,3133.5 8505.91,3127.6 U11.4@8582.76,3127.6 8580,3124.84 8580,3075 8596.48,3058.52 C99.2@8596.48,3027.43 8550.93,3027.43 R94.1@8495,2971.5
NetC67_2: C67.2 C99.1 R93.1 R101.2 U11.3 | length 397.3
  Bottom Layer w20: R93.1@8765,2981.5 8719.07,3027.43 C99.1@8659.47,3027.43 8659.47,3074.47 8675,3090 8675,3125.35 U11.3@8677.24,3127.6 8754.09,3127.6 C67.2@8760,3133.5 R101.2@8840,3133.5
NetC72_1: C72.1 D23.2 D25.1 | length 268.8
  Bottom Layer w30: C72.1@6750,4236.18 6791.3,4194.88 D25.1@6850,4194.88 6950,4294.88 D23.2@6950,4305.12
NetC72_2: C72.2 R91.1 | length 85.8
  Bottom Layer w30: C72.2@6750,4299.17 R91.1@6750,4385
NetC77_1: C77.1 C78.2 | length 91.3
  Bottom Layer w50: C77.1@3116.85,1040 C78.2@3208.15,1040
NetC79_1: C79.1 U2.3 U2.4 | length 232
  Bottom Layer w12: C79.1@1533.5,5068.11 1600.43,5068.11 1625.24,5092.92 U2.3@1729.68,5092.92 U2.4@1729.68,5118.51
NetC80_1: C80.1 Q35.1 R105.1 R107.2 | length 224.4
  Bottom Layer w20: Q35.1@4242.6,5267.24 4240,5269.84 R105.1@4240,5348.5 4248.5,5340 R107.2@4308.5,5340 C80.1@4308.5,5410
NetC81_2: C81.2 R110.2 | length 71.6
  Bottom Layer w15: R110.2@6631.5,4900 C81.2@6703.07,4900
NetC82_1: C82.1 R109.2 R111.1 U4.7 | length 297.2
  Bottom Layer w15: R111.1@5938.5,4370 R109.2@5938.5,4450 5940,4451.5 5940,4570 5966.79,4596.79 U4.7@5966.79,4655.51
NetC82_2: C82.2 C86.1 R67.2 R109.1 U4.6 | length 697.9
  Bottom Layer w15: C82.2@6000,4531.5 6000,4570 6016.79,4586.79 U4.6@6016.79,4655.51 6020,4658.72 6020,4730 6027.09,4737.09 6088.25,4737.09 6135.33,4690 6180,4690 6260,4770 R67.2@6260,4808.5 ; R109.1@6001.5,4450 C82.2@6001.5,4530 C86.1@6078.5,4530
NetC83_1: C83.1 C85.1 R65.1 R110.1 U4.2 | length 999.7
  Top Layer w15: v1(6297.5,4927.5) 6533.05,4927.5 6570,4890.55 v1(6570,4855)
  Bottom Layer w15: C83.1@5901.5,4970 5970,4970 ; U4.2@5966.79,4844.49 5970,4847.7 5970,4920 ; C85.1@6008.5,4970 5970,4970 ; R65.1@6358.5,4940 R65.1@6358.5,4940 6346,4927.5 v1(6297.5,4927.5) 6290,4920 5970,4920 ; R110.1@6568.5,4900 6568.5,4861.5 6570,4860 v1(6570,4855) ; 5970,4920 5970,4970
NetC83_2: C83.2 D29.3 D30.1 U4.1 | length 980
  Top Layer w20: v1(5820,4820) 5820,4778.52 5958.52,4640 v1(6190,4640)
  Bottom Layer w20: v1(5820,4820) 5892.3,4820 U4.1@5916.79,4844.49 5841.28,4920 5840,4920 5838.5,4921.5 C83.2@5838.5,4970 ; v1(6190,4640) 6215.35,4640 D30.1@6242.6,4667.24 6325.35,4750 D29.3@6390,4750
NetC86_2: C86.2 D30.3 R112.2 U4.5 | length 450.3
  Bottom Layer w20: U4.5@6066.79,4655.51 6094.49,4655.51 6140,4610 6140,4570 ; C86.2@6141.5,4530 6140,4531.5 6140,4570 ; R112.2@6410,4588.5 6295.75,4588.5 D30.3@6280,4572.76 6142.76,4572.76 6140,4570
NetC88_1: C88.1 R111.2 R113.2 | length 187.4
  Bottom Layer w15: R111.2@6001.5,4370 C88.1@6100,4370 6100,4400 6078.5,4421.5 R113.2@6078.5,4450
NetC90_1: C90.1 J9.1 J10.1 S1.3 U14.7 | length 2770.1
  Top Layer w15: v1(9690,5250) 9715,5250 9745,5220 9745,5050 v1(9775,5020) ; v1(9890,5020) 9890,5105 9900,5115 9900,5195 9920,5215 9963.11,5215 10009.06,5169.06 10024.06,5169.06 J9.1@10077.56,5115.55 ; 10005,5165 9960,5120 9960,4770 10015,4715 10070,4715 10115,4670 10115,4505 10077.56,4467.56 J10.1@10077.56,4340.55
  Bottom Layer w15: U14.7@9525.02,5329.38 9565.62,5329.38 9590,5305 9590,5255 9599.62,5245.38 9605.3,5245.38 9607.81,5247.89 C90.1@9632.5,5247.89 9634.62,5250 v1(9690,5250) ; v1(9775,5020) v1(9890,5020) ; S1.3@10000,3700 10000,3780 9980,3800 9980,3940 10075,4035 10105,4035 10140,4070 10140,4320 10119.45,4340.55 J10.1@10077.56,4340.55
NetC91_2: C91.2 J9.2 J10.2 R116.1 U14.6 | length 2642.2
  Top Layer w15: v1(9705,5380) 9635.88,5310.88 9632.5,5310.88 9632.5,5086.2 9763.7,4955 v1(9765,4955) v1@9775,4955 ; v1(9890,4955) 9930,4955 ; v1(9950,5175) 9930,5155 9930,4955 ; J10.2@10007.48,4300.39 9964.61,4300.39 9930,4335 9930,4955
  Bottom Layer w15: U14.6@9525.02,5379.38 9549.38,5379.38 9605.88,5435.88 C91.2@9632.5,5435.88 9669.12,5435.88 9690,5415 9690,5395 v1(9705,5380) ; v1(9765,4955) v1(9890,4955) ; R116.1@9875,3717.09 9875,3845 9945,3915 9945,4280 9965,4300 9970,4300 9970.39,4300.39 J10.2@10007.48,4300.39 ; v1@9950,5165 9950,5132.87 J9.2@10007.48,5075.39
NetC95_1: C95.1 D32.3 Q36.1 R119.2 | length 227.4
  Bottom Layer w15: C95.1@9375,4468.5 9402.27,4468.5 ; D32.3@9400,4397.24 9400,4466.24 9402.27,4468.5 ; Q36.1@9527.76,4462.6 9455.91,4462.6 R119.2@9450,4468.5 9402.27,4468.5
NetC96_1: C96.1 C98.1 J9.4 J9.5 J10.4 J10.5 R123.2 R124.2 | length 2077.1
  Top Layer w15: v1(9900,4235) 9992.56,4235 J10.4@10007.48,4220.08
  Bottom Layer w15: R124.2@9643.5,5815 C96.1@9643.5,5740 R123.2@9643.5,5670 C98.1@9643.5,5600 9643.5,5591.5 9725,5510 9725,5430 9900,5255 9900,5080 9984.92,4995.08 J9.4@10007.48,4995.08 ; v1(9900,4235) 9900,4250 9905,4255 9905,4300 9930,4325 9930,4917.6 J9.4@10007.48,4995.08 ; J10.4@10007.48,4220.08 10012.56,4215 10040,4215 10075.08,4179.92 J10.5@10077.56,4179.92 ; J9.5@10077.56,4954.92 10045,4987.48 10045,4990 10012.56,4990 J9.4@10007.48,4995.08
NetC97_1: C97.1 D33.3 Q38.1 R122.2 | length 228.5
  Bottom Layer w15: C97.1@9375,4993.5 9405,4993.5 ; D33.3@9400,4922.24 9400,4988.5 9405,4993.5 ; Q38.1@9527.76,4987.6 9455.91,4987.6 R122.2@9450,4993.5 9405,4993.5
NetC100_1: C100.1 R125.1 | length 122.7
  Bottom Layer w60: R125.1@5675,859.45 5707.09,827.36 C100.1@5707.09,750
NetC101_1: C101.1 R126.1 | length 151.5
  Bottom Layer w60: R126.1@6550,874.86 6555.14,874.86 6607.09,822.91 C101.1@6607.09,750
NetC102_1: C102.1 R127.1 | length 115.7
  Bottom Layer w59.06: C102.1@6522.91,3670 6522.91,3592.64 R127.1@6550,3565.55
NetC103_1: C103.1 R128.1 | length 115.7
  Bottom Layer w60: R128.1@5675,3565.55 5702.09,3592.64 C103.1@5702.09,3670
NetD1_2: D1.2 D3.2 R2.1 U2.2 | length 1128.7
  Top Layer w12: v3(1111.44,5304.15) 1442.77,5304.15 1502.01,5244.92 1502.01,5087.8 v3(1600.43,4989.37)
  Bottom Layer w12: D3.2@1029.57,5320.08 1045.49,5304.15 v3(1111.44,5304.15) 1171.12,5304.15 D1.2@1187.05,5320.08 ; R2.1@1533.5,4989.37 1582.31,4989.37 ; v3(1600.43,4989.37) 1582.31,4989.37 ; U2.2@1729.68,5067.33 1660.27,5067.33 1582.31,4989.37
NetD2_3: D2.3 R27.2 R34.2 | length 1223
  Top Layer w12: v3(1750,4750) 1853.19,4750 1856.34,4753.15 2289.41,4753.15 2348.46,4812.2 v3(2348.46,5146.85)
  Bottom Layer w12: D2.3@1662.4,4750 v3(1750,4750) ; R27.2@2281.54,5146.85 v3(2348.46,5146.85)
  Bottom Layer w39.37: v3(1750,4750) 1855.16,4750 R34.2@1858.31,4753.15
NetD4_3: D4.3 D21.3 R53.1 | length 216.3
  Bottom Layer w20: R53.1@9215,3735 9217.24,3737.24 D21.3@9350,3737.24 D4.3@9350,3817.6
NetD5_3: D5.3 R59.2 U5.7 | length 688.2
  Top Layer w12: v3(4258.27,4379.49) 4258.27,4548.78 4298.86,4589.37 v3(4298.86,4739.77)
  Bottom Layer w12: U5.7@4155.42,4478.55 4224.21,4478.55 4258.27,4444.49 ; v3(4258.27,4379.49) 4258.27,4444.49 ; R59.2@4305.51,4444.49 4258.27,4444.49
  Bottom Layer w20: D5.3@4216.93,4739.77 v3(4298.86,4739.77)
NetD7_1: D7.1 Q8.2 Q9.2 T1.3
NetD7_2: D7.2 D10.1 J19.1 T4.1 T7.4 T7.5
